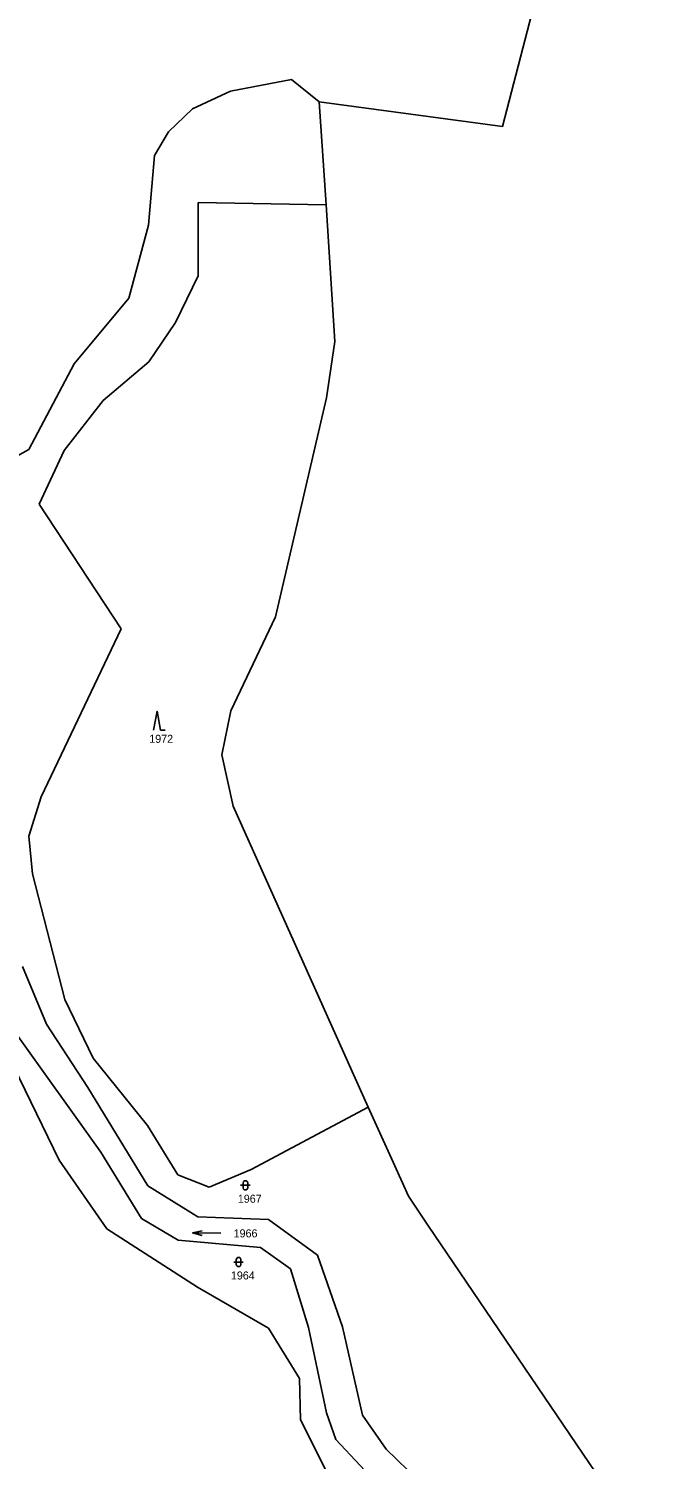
# Model space of a CAD drawing. Extents: x -802857 to -799647, y -1020285 to -1015884.
# Drawn here: x -801308.3 to -801173.6, y -1016866.1 to -1016562.1 of the extents above; entities that cross this region are included whole.
import ezdxf

# ---------------------------------------------------------------- set-up
doc = ezdxf.new("R2010")
doc.units = 0
for name, color, linetype in [('Default', 7, 'Continuous'), ('KN_HRANICE', 7, 'Continuous'), ('KN_KULTURY', 7, 'Continuous'), ('KN_PARCELY', 7, 'Continuous')]:
    doc.layers.add(name, color=color, linetype=linetype)

# ---------------------------------------------------------------- blocks, each defined once
blk = doc.blocks.new('308')
at = {"layer": 'Default'}
blk.add_lwpolyline([(-0.75, 0), (0, 4), (0.75, 0), (1.75, 0)], dxfattribs=at)
blk = doc.blocks.new('316')
at = {"layer": 'Default'}
for points in [[(-1, 1), (0.27, 1), (1, 1)], [(-0.5, 1.5), (-0.4, 1.79), (-0.15, 1.97), (0.16, 1.97), (0.41, 1.79), (0.51, 1.5), (0.51, 0.5), (0.41, 0.21), (0.16, 0.03), (-0.15, 0.03), (-0.4, 0.21), (-0.5, 0.5), (-0.5, 1.5)]]:
    blk.add_lwpolyline(points, dxfattribs=at)
blk = doc.blocks.new('802')
at = {"layer": 'Default'}
blk.add_line((-3, 0), (3, 0), dxfattribs=at)
blk.add_lwpolyline([(1, 0.5), (3, 0), (1, -0.5)], dxfattribs=at)

msp = doc.modelspace()

# ---------------------------------------------------------------- linework, layer by layer
at = {"layer": 'KN_HRANICE'}
for p, q in [((-801196.12, -1016537.94), (-801207.69, -1016582.91)), ((-801265.48, -1016575.38), (-801252.47, -1016572.88)), ((-801252.47, -1016572.88), (-801246.59, -1016577.62)), ((-801273.5, -1016579.11), (-801265.48, -1016575.38)), ((-801278.62, -1016584.04), (-801273.5, -1016579.11)), ((-801246.59, -1016577.62), (-801245.16, -1016599.53)), ((-801207.69, -1016582.91), (-801246.59, -1016577.62)), ((-801281.61, -1016589.02), (-801278.62, -1016584.04)), ((-801282.88, -1016603.88), (-801281.61, -1016589.02)), ((-801245.16, -1016599.53), (-801272.31, -1016599.02)), ((-801272.31, -1016599.02), (-801272.29, -1016614.6)), ((-801245.16, -1016599.53), (-801243.27, -1016628.57)), ((-801287.04, -1016619.33), (-801282.88, -1016603.88)), ((-801272.29, -1016614.6), (-801277.12, -1016624.55)), ((-801298.6, -1016633.32), (-801287.04, -1016619.33)), ((-801277.12, -1016624.55), (-801282.8, -1016632.88)), ((-801243.27, -1016628.57), (-801245.06, -1016640.51)), ((-801308.25, -1016651.49), (-801298.6, -1016633.32)), ((-801282.8, -1016632.88), (-801292.46, -1016641.08)), ((-801255.91, -1016687.07), (-801245.06, -1016640.51)), ((-801292.46, -1016641.08), (-801300.77, -1016651.72)), ((-801323.26, -1016659.76), (-801308.25, -1016651.49)), ((-801300.77, -1016651.72), (-801306.09, -1016663.1)), ((-801306.09, -1016663.1), (-801288.67, -1016689.61)), ((-801255.91, -1016687.07), (-801265.38, -1016707.01)), ((-801288.67, -1016689.61), (-801305.61, -1016725.29)), ((-801265.38, -1016707.01), (-801267.26, -1016716.41)), ((-801267.26, -1016716.41), (-801264.86, -1016727.26)), ((-801305.61, -1016725.29), (-801308.25, -1016733.62)), ((-801264.86, -1016727.26), (-801236.19, -1016791.22)), ((-801308.25, -1016733.62), (-801307.47, -1016741.69)), ((-801307.47, -1016741.69), (-801300.62, -1016768.35)), ((-801304.52, -1016773.59), (-801309.57, -1016761.31)), ((-801300.62, -1016768.35), (-801294.6, -1016780.8)), ((-801295.75, -1016787.05), (-801304.52, -1016773.59)), ((-801292.99, -1016800.81), (-801310.89, -1016775.73)), ((-801313.82, -1016777.7), (-801301.84, -1016802.52)), ((-801294.6, -1016780.8), (-801283.09, -1016795.11)), ((-801282.99, -1016807.91), (-801295.75, -1016787.05)), ((-801236.19, -1016791.22), (-801261.04, -1016804.5)), ((-801236.19, -1016791.22), (-801230.93, -1016802.94)), ((-801283.09, -1016795.11), (-801276.64, -1016805.63)), ((-801284.31, -1016814.88), (-801292.99, -1016800.81)), ((-801301.84, -1016802.52), (-801291.71, -1016817.07)), ((-801270, -1016808.23), (-801261.04, -1016804.5)), ((-801230.93, -1016802.94), (-801227.69, -1016810.17)), ((-801276.64, -1016805.63), (-801270, -1016808.23)), ((-801272.38, -1016814.51), (-801282.99, -1016807.91)), ((-801227.69, -1016810.17), (-801223.54, -1016816.29)), ((-801276.59, -1016819.48), (-801284.31, -1016814.88)), ((-801257.35, -1016815.11), (-801272.38, -1016814.51)), ((-801246.96, -1016822.66), (-801257.35, -1016815.11)), ((-801223.54, -1016816.29), (-801173.56, -1016890)), ((-801291.71, -1016817.07), (-801272.46, -1016829.44)), ((-801259.11, -1016821.03), (-801276.59, -1016819.48)), ((-801252.7, -1016825.56), (-801259.11, -1016821.03)), ((-801241.66, -1016837.9), (-801246.96, -1016822.66)), ((-801248.92, -1016838.05), (-801252.7, -1016825.56)), ((-801272.46, -1016829.44), (-801257.35, -1016838.15)), ((-801257.35, -1016838.15), (-801250.82, -1016848.86)), ((-801245.06, -1016856.14), (-801248.92, -1016838.05)), ((-801237.39, -1016856.65), (-801241.66, -1016837.9)), ((-801250.82, -1016848.86), (-801250.6, -1016857.65)), ((-801243.11, -1016861.82), (-801245.06, -1016856.14)), ((-801250.6, -1016857.65), (-801243.71, -1016871.35)), ((-801232.37, -1016863.85), (-801237.39, -1016856.65)), ((-801230.06, -1016875.69), (-801243.11, -1016861.82)), ((-801222, -1016873.95), (-801232.37, -1016863.85))]:
    msp.add_line(p, q, dxfattribs=at)

# ---------------------------------------------------------------- block references
at = {"layer": 'KN_KULTURY'}
for name, p in [('308', (-801281.03, -1016711.12)), ('316', (-801262.29, -1016808.83)), ('316', (-801263.73, -1016825.13))]:
    msp.add_blockref(name, p, dxfattribs=at)
at = {"layer": 'KN_KULTURY', "rotation": 179.221198}
msp.add_blockref('802', (-801270.48, -1016817.99), dxfattribs=at)

# ---------------------------------------------------------------- texts
at = {"layer": 'KN_PARCELY'}
for s, p in [('1972', (-801282.69, -1016713.82)), ('1967', (-801263.89, -1016811.53)), ('1966', (-801264.78, -1016818.89)), ('1964', (-801265.36, -1016827.83))]:
    msp.add_text(s, height=1.7, dxfattribs=at).set_placement(p)

doc.saveas('drawing.dxf')
